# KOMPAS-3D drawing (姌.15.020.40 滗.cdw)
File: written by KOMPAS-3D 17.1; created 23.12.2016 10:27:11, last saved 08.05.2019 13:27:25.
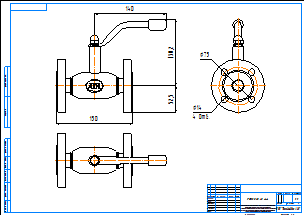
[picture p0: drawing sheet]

Sheet 1: A2, landscape

Title block, sheet 1: name: КШ.15.020.40 фф; material: Внимание! Данный продукт является объектом авторского права ООО «Торговый Дом АДЛ». / Запрещается изменение, копирование, распространение / (в том числе путем копирования на другие сайты и ресурсы в Интернете) / или любое иное использование информации и объектов без предварительного / согласия правообладателя (ООО «Торговый Дом АДЛ»).; sheets: 1; organisation: ООО "Торговый дом АДЛ"; sheet format: A2; stored path: C:\Users\tra\Desktop\2д чертежи\Шаровые краны БИВАЛ\КШ_Бивал_серия_14_15\KOMPAS_2D\КШ.15.020.40 фф.cdw

Views: Вид 1, Проекционный вид 2, Проекционный вид 3, Спереди 4, Проекционный вид 5, Проекционный вид 6
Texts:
  Klimkovich
  ADL
Dimensions and other numbers on the sheet: 150; 140; 130,2; 52,5; 75; 14; 4 Отв.; 1:1; 1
